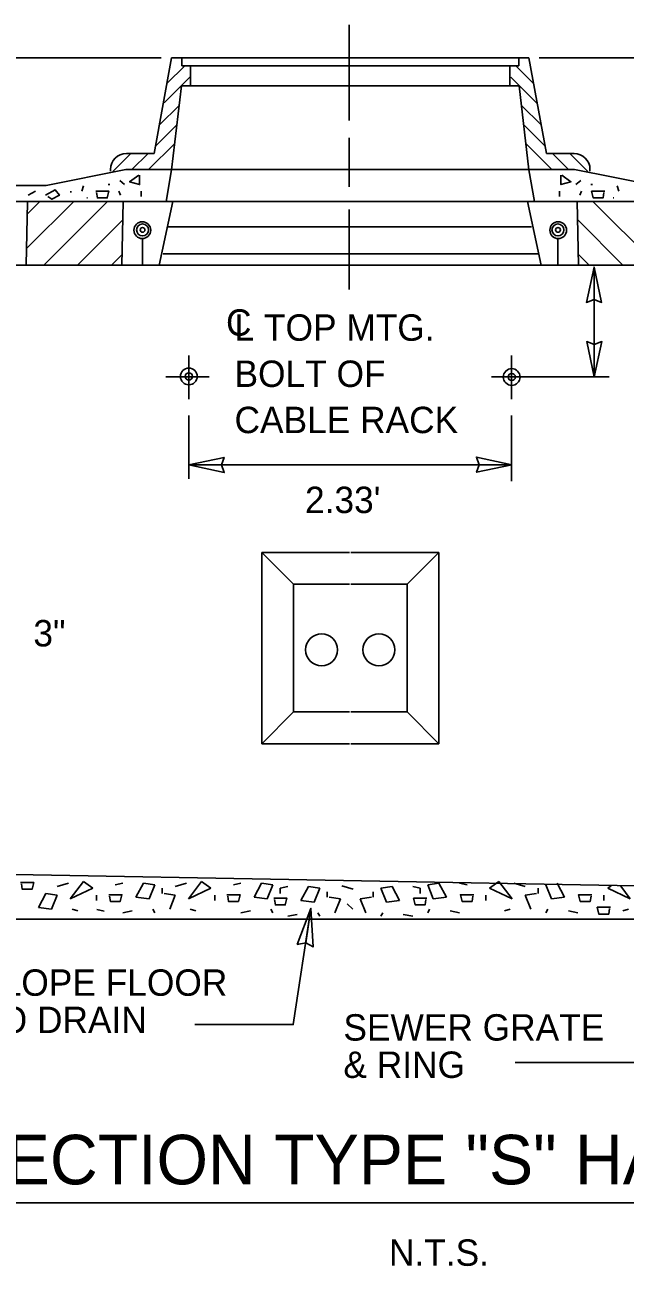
# Model space of a CAD drawing. Extents: x 19188 to 19495, y 20866 to 21061.
# Drawn here: x 19216.59 to 19235.64, y 20976.7 to 21016.09 of the extents above; entities that cross this region are included whole.
import ezdxf

# ---------------------------------------------------------------- set-up
doc = ezdxf.new("R2010")
doc.units = 0
doc.layers.add('G-ANNO-NOTE', color=7, linetype='Continuous')

msp = doc.modelspace()

# ---------------------------------------------------------------- linework, layer by layer
at = {"layer": 'G-ANNO-NOTE'}
for p, q in [((19220.92, 21015.045), (19211.963, 21015.045)), ((19221.25, 21015.045), (19220.696, 21012.007)), ((19221.1, 21014.227), (19221.666, 21014.791)), ((19221.25, 21015.045), (19226.92, 21015.045)), ((19221.574, 21015.045), (19221.574, 21014.791)), ((19221.574, 21014.791), (19226.92, 21014.791)), ((19221.853, 21014.791), (19221.853, 21014.175)), ((19232.589, 21015.045), (19226.92, 21015.045)), ((19232.266, 21014.791), (19226.92, 21014.791)), ((19231.987, 21014.791), (19231.987, 21014.175)), ((19232.738, 21014.227), (19232.173, 21014.791)), ((19232.266, 21015.045), (19232.266, 21014.791)), ((19232.589, 21015.045), (19233.143, 21012.007)), ((19232.92, 21015.045), (19252.718, 21015.045)), ((19221.014, 21013.614), (19221.827, 21014.426)), ((19232.825, 21013.614), (19232.012, 21014.426)), ((19221.25, 21011.494), (19221.559, 21014.159)), ((19221.559, 21014.159), (19226.92, 21014.159)), ((19232.281, 21014.159), (19226.92, 21014.159)), ((19232.589, 21011.494), (19232.281, 21014.159)), ((19220.861, 21012.913), (19221.484, 21013.536)), ((19232.978, 21012.913), (19232.355, 21013.536)), ((19221.412, 21012.922), (19220.755, 21012.266)), ((19232.427, 21012.922), (19233.083, 21012.266)), ((19220.53, 21011.508), (19221.339, 21012.317)), ((19233.309, 21011.508), (19232.501, 21012.317)), ((19219.383, 21011.435), (19219.955, 21012.007)), ((19219.817, 21012.007), (19220.696, 21012.007)), ((19220.01, 21011.52), (19220.48, 21011.99)), ((19234.022, 21012.007), (19233.143, 21012.007)), ((19233.829, 21011.52), (19233.359, 21011.99)), ((19234.456, 21011.435), (19233.884, 21012.007)), ((19219.798, 21011.501), (19217.267, 21010.995)), ((19219.311, 21011.447), (19219.311, 21011.501)), ((19219.798, 21011.501), (19234.041, 21011.501)), ((19221.25, 21011.494), (19221.073, 21010.482)), ((19232.589, 21011.494), (19232.766, 21010.482)), ((19234.041, 21011.501), (19236.572, 21010.995)), ((19234.528, 21011.447), (19234.528, 21011.501)), ((19211.192, 21010.995), (19217.267, 21010.995)), ((19211.192, 21010.489), (19242.647, 21010.489)), ((19216.636, 21008.478), (19216.675, 21010.468)), ((19218.143, 21010.489), (19216.655, 21009)), ((19217.069, 21010.489), (19216.673, 21010.092)), ((19217.192, 21008.464), (19219.217, 21010.489)), ((19219.673, 21008.464), (19219.714, 21010.489)), ((19221.29, 21010.482), (19220.856, 21008.467)), ((19232.549, 21010.482), (19232.983, 21008.467)), ((19234.166, 21008.464), (19234.126, 21010.489)), ((19236.647, 21008.464), (19234.622, 21010.489)), ((19218.266, 21008.464), (19219.702, 21009.899)), ((19221.135, 21009.676), (19232.676, 21009.676)), ((19235.573, 21008.464), (19234.137, 21009.899)), ((19220.327, 21009.314), (19220.327, 21008.491)), ((19233.512, 21009.314), (19233.512, 21008.491)), ((19219.34, 21008.464), (19219.68, 21008.804)), ((19220.98, 21008.819), (19232.914, 21008.819)), ((19226.899, 21008.819), (19226.899, 21008.819)), ((19226.94, 21008.819), (19226.94, 21008.819)), ((19234.499, 21008.464), (19234.159, 21008.804)), ((19211.192, 21008.464), (19242.647, 21008.464)), ((19219.978, 21008.462), (19220.615, 21008.462)), ((19233.861, 21008.462), (19233.224, 21008.462)), ((19234.658, 21004.92), (19234.658, 21008.402)), ((19234.658, 21008.402), (19234.658, 21007.372)), ((19234.658, 21004.92), (19234.658, 21005.95)), ((19221.798, 21005.594), (19221.798, 21004.213)), ((19232.041, 21005.594), (19232.041, 21004.213)), ((19221.07, 21004.92), (19222.439, 21004.92)), ((19235.141, 21004.92), (19231.4, 21004.92)), ((19221.798, 21003.698), (19221.798, 21001.682)), ((19232.041, 21003.698), (19232.041, 21001.608)), ((19221.798, 21002.13), (19232.044, 21002.13)), ((19221.798, 21002.13), (19222.829, 21002.13)), ((19232.044, 21002.13), (19231.014, 21002.13)), ((19224.112, 20999.351), (19226.899, 20999.351)), ((19224.112, 20999.351), (19224.112, 20993.276)), ((19225.114, 20998.339), (19224.112, 20999.351)), ((19229.727, 20999.351), (19226.94, 20999.351)), ((19228.725, 20998.339), (19229.727, 20999.351)), ((19229.727, 20999.351), (19229.727, 20993.276)), ((19225.114, 20998.339), (19225.114, 20994.289)), ((19225.114, 20998.339), (19226.899, 20998.339)), ((19228.725, 20998.339), (19226.94, 20998.339)), ((19228.725, 20998.339), (19228.725, 20994.289)), ((19225.114, 20994.289), (19224.112, 20993.276)), ((19225.114, 20994.289), (19226.899, 20994.289)), ((19228.725, 20994.289), (19226.94, 20994.289)), ((19228.725, 20994.289), (19229.727, 20993.276)), ((19224.112, 20993.276), (19226.899, 20993.276)), ((19229.727, 20993.276), (19226.94, 20993.276)), ((19211.192, 20989.226), (19240.021, 20988.692)), ((19217.617, 20988.745), (19217.975, 20988.855)), ((19218.034, 20988.358), (19218.451, 20988.911)), ((19218.748, 20988.69), (19218.034, 20988.358)), ((19218.451, 20988.911), (19218.748, 20988.69)), ((19219.462, 20988.8), (19219.701, 20988.855)), ((19220.118, 20988.413), (19220.355, 20988.855)), ((19220.355, 20988.855), (19220.713, 20988.8)), ((19220.713, 20988.8), (19220.534, 20988.358)), ((19220.951, 20988.524), (19220.951, 20988.69)), ((19221.367, 20988.745), (19221.724, 20988.855)), ((19221.784, 20988.358), (19222.2, 20988.911)), ((19222.498, 20988.69), (19221.784, 20988.358)), ((19222.2, 20988.911), (19222.498, 20988.69)), ((19223.212, 20988.8), (19223.45, 20988.855)), ((19223.867, 20988.413), (19224.105, 20988.855)), ((19224.105, 20988.855), (19224.462, 20988.8)), ((19224.462, 20988.8), (19224.284, 20988.358)), ((19224.7, 20988.69), (19224.938, 20988.745)), ((19224.7, 20988.524), (19224.7, 20988.69)), ((19225.355, 20988.303), (19225.593, 20988.745)), ((19225.593, 20988.745), (19225.95, 20988.69)), ((19225.95, 20988.69), (19225.771, 20988.248)), ((19227.012, 20988.661), (19226.655, 20988.772)), ((19228.246, 20988.745), (19227.889, 20988.69)), ((19227.889, 20988.69), (19228.067, 20988.248)), ((19228.484, 20988.303), (19228.246, 20988.745)), ((19229.139, 20988.69), (19228.901, 20988.745)), ((19229.139, 20988.524), (19229.139, 20988.69)), ((19229.734, 20988.855), (19229.377, 20988.8)), ((19229.377, 20988.8), (19229.555, 20988.358)), ((19229.972, 20988.413), (19229.734, 20988.855)), ((19230.627, 20988.8), (19230.389, 20988.855)), ((19231.639, 20988.911), (19231.341, 20988.69)), ((19231.341, 20988.69), (19232.055, 20988.358)), ((19232.055, 20988.358), (19231.639, 20988.911)), ((19232.472, 20988.745), (19232.115, 20988.855)), ((19232.888, 20988.524), (19232.888, 20988.69)), ((19233.127, 20988.8), (19233.305, 20988.358)), ((19233.722, 20988.413), (19233.484, 20988.855)), ((19235.197, 20988.769), (19235.09, 20988.69)), ((19235.09, 20988.69), (19235.805, 20988.358)), ((19235.805, 20988.358), (19235.502, 20988.759)), ((19217.023, 20988.082), (19217.261, 20988.524)), ((19217.261, 20988.524), (19217.617, 20988.469)), ((19217.617, 20988.469), (19217.439, 20988.027)), ((19218.868, 20988.303), (19218.868, 20988.469)), ((19220.534, 20988.358), (19220.118, 20988.413)), ((19221.01, 20988.524), (19221.367, 20988.469)), ((19221.367, 20988.469), (19221.189, 20988.027)), ((19222.617, 20988.303), (19222.617, 20988.469)), ((19224.284, 20988.358), (19223.867, 20988.413)), ((19225.771, 20988.248), (19225.355, 20988.303)), ((19226.188, 20988.413), (19226.188, 20988.579)), ((19226.248, 20988.413), (19226.605, 20988.358)), ((19226.605, 20988.358), (19226.426, 20987.916)), ((19227.591, 20988.413), (19227.234, 20988.358)), ((19227.234, 20988.358), (19227.413, 20987.916)), ((19227.651, 20988.413), (19227.651, 20988.579)), ((19228.067, 20988.248), (19228.484, 20988.303)), ((19229.555, 20988.358), (19229.972, 20988.413)), ((19231.222, 20988.303), (19231.222, 20988.469)), ((19232.829, 20988.524), (19232.472, 20988.469)), ((19232.472, 20988.469), (19232.651, 20988.027)), ((19233.305, 20988.358), (19233.722, 20988.413)), ((19234.972, 20988.303), (19234.972, 20988.469)), ((19217.439, 20988.027), (19217.023, 20988.082)), ((19218.272, 20987.971), (19218.094, 20988.027)), ((19219.109, 20987.963), (19218.871, 20988.019)), ((19219.701, 20987.916), (19219.998, 20987.971)), ((19220.713, 20987.916), (19220.653, 20988.027)), ((19222.022, 20987.971), (19221.843, 20988.027)), ((19223.45, 20987.916), (19223.748, 20987.971)), ((19224.462, 20987.916), (19224.403, 20988.027)), ((19225.95, 20987.806), (19225.891, 20987.916)), ((19226.82, 20988.199), (19226.999, 20988.034)), ((19227.889, 20987.806), (19227.949, 20987.916)), ((19229.377, 20987.916), (19229.436, 20988.027)), ((19230.389, 20987.916), (19230.091, 20987.971)), ((19231.817, 20987.971), (19231.996, 20988.027)), ((19233.127, 20987.916), (19233.186, 20988.027)), ((19234.138, 20987.916), (19233.841, 20987.971)), ((19235.567, 20987.971), (19235.745, 20988.027)), ((19207.649, 20987.708), (19249.414, 20987.708)), ((19224.938, 20987.806), (19225.236, 20987.861)), ((19228.901, 20987.806), (19228.603, 20987.861)), ((19213.987, 20978.708), (19246.848, 20978.708))]:
    msp.add_line(p, q, dxfattribs=at)
for points in [[(19226.886, 21016.091), (19226.886, 21013.053)], [(19226.886, 21012.5), (19226.886, 21010.953)], [(19219.602, 21011.152), (19219.759, 21011.024)], [(19220.205, 21011.322), (19219.917, 21011.109), (19220.231, 21011.024), (19220.231, 21011.322)], [(19233.633, 21011.322), (19233.922, 21011.109), (19233.607, 21011.024), (19233.607, 21011.322)], [(19234.236, 21011.152), (19234.079, 21011.024)], [(19216.693, 21010.683), (19216.928, 21010.811)], [(19217.243, 21010.683), (19217.558, 21010.853), (19217.689, 21010.683), (19217.453, 21010.556), (19217.322, 21010.641)], [(19218.056, 21010.768), (19218.056, 21010.811)], [(19218.396, 21010.811), (19218.449, 21010.981)], [(19218.842, 21010.811), (19219.262, 21010.811), (19219.209, 21010.598), (19218.895, 21010.598), (19218.868, 21010.768)], [(19219.288, 21011.024), (19219.236, 21011.024)], [(19219.628, 21010.683), (19219.576, 21010.811)], [(19220.284, 21010.641), (19220.284, 21010.811)], [(19233.555, 21010.641), (19233.555, 21010.811)], [(19234.21, 21010.683), (19234.263, 21010.811)], [(19234.551, 21011.024), (19234.604, 21011.024)], [(19234.997, 21010.811), (19234.577, 21010.811), (19234.63, 21010.598), (19234.945, 21010.598), (19234.971, 21010.768)], [(19235.442, 21010.811), (19235.39, 21010.981)], [(19218.58, 21010.598), (19218.554, 21010.598)], [(19235.259, 21010.598), (19235.285, 21010.598)], [(19226.886, 21007.694), (19226.886, 21010.235)], [(19234.658, 21007.371), (19234.412, 21007.281), (19234.658, 21008.402), (19234.894, 21007.284), (19234.658, 21007.371)], [(19234.658, 21005.951), (19234.905, 21006.041), (19234.658, 21004.92), (19234.424, 21006.038), (19234.658, 21005.951)], [(19222.829, 21002.131), (19222.919, 21001.884), (19221.798, 21002.13), (19222.917, 21002.366), (19222.829, 21002.131)], [(19231.013, 21002.13), (19230.923, 21002.376), (19232.044, 21002.13), (19230.926, 21001.895), (19231.013, 21002.13)], [(19232.151, 20983.165), (19236.381, 20983.165), (19239.304, 20989.091)], [(19216.456, 20988.873), (19216.875, 20988.873), (19216.822, 20988.66), (19216.508, 20988.66), (19216.482, 20988.83)], [(19219.253, 20988.486), (19219.672, 20988.486), (19219.62, 20988.273), (19219.305, 20988.273), (19219.279, 20988.443)], [(19223.003, 20988.486), (19223.422, 20988.486), (19223.369, 20988.273), (19223.055, 20988.273), (19223.029, 20988.443)], [(19224.491, 20988.376), (19224.91, 20988.376), (19224.857, 20988.162), (19224.543, 20988.162), (19224.517, 20988.333)], [(19229.348, 20988.376), (19228.929, 20988.376), (19228.982, 20988.162), (19229.296, 20988.162), (19229.322, 20988.333)], [(19230.837, 20988.486), (19230.417, 20988.486), (19230.469, 20988.273), (19230.784, 20988.273), (19230.811, 20988.443)], [(19234.586, 20988.486), (19234.167, 20988.486), (19234.219, 20988.273), (19234.534, 20988.273), (19234.56, 20988.443)], [(19221.989, 20984.366), (19225.111, 20984.366), (19225.672, 20988.05)], [(19235.175, 20988.088), (19234.756, 20988.088), (19234.808, 20987.874), (19235.122, 20987.874), (19235.149, 20988.045)]]:
    msp.add_lwpolyline(points, dxfattribs=at)
msp.add_lwpolyline([(19225.231, 20986.907), (19225.506, 20986.963), (19225.672, 20988.05), (19225.74, 20986.833), (19225.506, 20986.963), (19225.672, 20988.05)], close=True, dxfattribs=at)
for centre, radius in [((19220.319, 21009.576), 0.266), ((19220.327, 21009.583), 0.19), ((19220.327, 21009.583), 0.0759), ((19233.52, 21009.576), 0.266), ((19233.512, 21009.583), 0.19), ((19233.512, 21009.583), 0.0759), ((19221.796, 21004.935), 0.266), ((19221.796, 21004.935), 0.114), ((19232.043, 21004.915), 0.266), ((19232.043, 21004.915), 0.114), ((19226.01, 20996.258), 0.506), ((19227.829, 20996.258), 0.506)]:
    msp.add_circle(centre, radius, dxfattribs=at)
for centre, start, end in [((19219.817, 21011.501), 90, 180), ((19234.022, 21011.501), 0, 90)]:
    msp.add_arc(centre, 0.506, start, end, dxfattribs=at)

# ---------------------------------------------------------------- texts
for s, height, p in [('C', 0.838, (19222.976, 21006.226)), ('L TOP MTG.', 0.8379, (19223.246, 21006.066)), ('BOLT OF ', 0.8379, (19223.246, 21004.6)), ('CABLE RACK', 0.8379, (19223.246, 21003.134)), ("2.33'", 0.8379, (19225.483, 21000.598)), ('3"', 0.8379, (19216.862, 20996.366)), ('SLOPE FLOOR ', 0.83785, (19215.11, 20985.28)), ('TO DRAIN', 0.8379, (19215.11, 20984.097)), ('SEWER GRATE', 0.83785, (19226.702, 20983.858)), ('& RING', 0.8379, (19226.702, 20982.674)), ('SECTION TYPE "S" HANDHOLE', 1.57098, (19214.585, 20979.297)), ('N.T.S.', 0.8379, (19228.147, 20976.712))]:
    msp.add_text(s, height=height, dxfattribs=at).set_placement(p)

doc.saveas('drawing.dxf')
